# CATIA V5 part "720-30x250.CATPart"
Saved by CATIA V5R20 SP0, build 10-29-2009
Part number: 720-30x250
Definition: NONE
Nomenclature: 720-30x250
Source: Unknown
Description: 720-30x250
Bounding box of the stored display mesh (mm): x 0 to 250, y -15 to 15, z -15 to 15
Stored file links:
  C:\Users\Utente\Desktop\IO LAVORO\3D X SITO CF\X SITO\720\720-30x250.CATPart

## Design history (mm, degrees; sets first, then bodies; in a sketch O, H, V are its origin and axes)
Body1 "720-30x250" (main body)
  Solid1: solid without history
